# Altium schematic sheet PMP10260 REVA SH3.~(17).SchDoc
size 431 x 279 mm; Date: Not shown in title block; ApprovedBy: Not shown in title block; CheckedBy: Not shown in title block; Author: Not shown in title block; CompanyName: Not shown in title block; Engineer: Not shown in title block; Organization: Not shown in title block; Address1: Not shown in title block; Address2: Not shown in title block; Address3: Not shown in title block; Address4: Not shown in title block; DocumentNumber: 3; Revision: Use project parameter SCH_Rev; SheetNumber: 3; SheetTotal: 4; PageSetup: Record=PageOptions|CenterHorizontal=True|CenterVertical=True|PrintScale=1.00|XCorrection=1.00|YCorrection=1.00|PrintKind=0|BorderSize=5000000|LeftOffset=0|BottomOffset=0|Orientation=2|PaperLength=1000|PaperWidth=1000|Scale=100|PaperSource=15|PrintQuality=600|MediaType=1|DitherType=10|PaperKind=Letter|PrintScaleMode=1
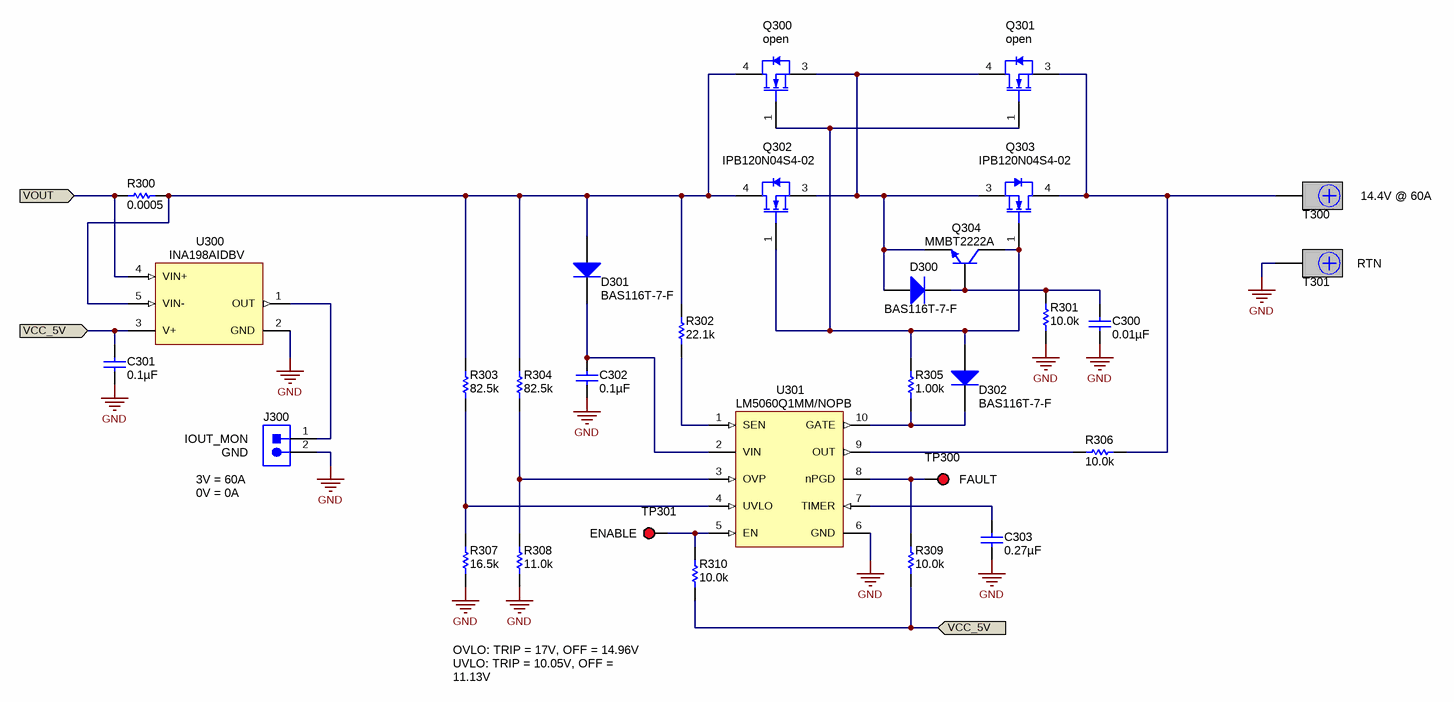
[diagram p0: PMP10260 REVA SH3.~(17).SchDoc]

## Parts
C300  ValueDisplayed: 0.01µF  [0603]  (hidden comment: C1608X7R1H103K)
C301  ValueDisplayed: 0.1µF  [0603L]  (hidden comment: C1608X7R1H104K)
C302  ValueDisplayed: 0.1µF  [0603L]  (hidden comment: C1608X7R1H104K)
C303  ValueDisplayed: 0.27µF  [0805_HV]  (hidden comment: 0805YC274KAT2A)
D300  BAS116T-7-F  [SOT-523]
D301  BAS116T-7-F  [SOT-523]
D302  BAS116T-7-F  [SOT-523]
J300  PEC02SAAN  [CONN_PEC02SAAN]  (value not drawn)
Q300  open  [DDPAK]
Q301  open  [DDPAK]
Q302  IPB120N04S4-02  [DDPAK]
Q303  IPB120N04S4-02  [DDPAK]
Q304  MMBT2222A  [SOT-23]
R300  value 0.0005  [CSS2725_0005]  (hidden comment: CSS2725FTL500)
R301  value 10.0k  [0603]  (hidden comment: CRCW060310K0FKEA)
R302  value 22.1k  [0603]  (hidden comment: CRCW060322K1FKEA)
R303  value 82.5k  [0603]  (hidden comment: CRCW060382K5FKEA)
R304  value 82.5k  [0603]  (hidden comment: CRCW060382K5FKEA)
R305  value 1.00k  [0603]  (hidden comment: CRCW06031K00FKEA)
R306  value 10.0k  [0603]  (hidden comment: CRCW060310K0FKEA)
R307  value 16.5k  [0603]  (hidden comment: CRCW060316K5FKEA)
R308  value 11.0k  [0603]  (hidden comment: CRCW060311K0FKEA)
R309  value 10.0k  [0603]  (hidden comment: CRCW060310K0FKEA)
R310  value 10.0k  [0603]  (hidden comment: CRCW060310K0FKEA)
T300  CB70-14-CY  [CB70-14-CY]  (value not drawn)
T301  CB70-14-CY  [CB70-14-CY]  (value not drawn)
TP300  5010  [Keystone5010]  (value not drawn)
TP301  5010  [Keystone5010]  (value not drawn)
U300  INA198AIDBV  [DBV0005A_N]
U301  LM5060Q1MM/NOPB  [MUB10A_N]

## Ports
VCC_5V, VOUT

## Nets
GND: C300.2 C301.2 C302.2 C303.2 J300.2 R301.1 R307.1 R308.1 T301.1 U300.2(GND) U301.6(GND)
VCC_5V: C301.1 R309.1 R310.1 U300.3(V+) ; port VCC_5V
VOUT: R300.1 U300.4(VIN+) ; port VOUT
NetC300_1: C300.1 D300.3(K) Q304.1(B) R301.2
NetC302_1: C302.1 D301.3(K) U301.2(VIN)
NetC303_1: C303.1 U301.7(TIMER)
NetD300_1: D300.1(A) Q300.3(S) Q301.4(D) Q302.3(S) Q303.3(S) Q304.2(E)
NetD301_1: D301.1(A) Q300.4(D) Q302.4(D) R300.2 R302.2 R303.2 R304.2 U300.5(VIN-)
NetD302_1: D302.1(A) Q300.1(G) Q301.1(G) Q302.1(G) Q303.1(G) Q304.3(C) R305.1
NetD302_3: D302.3(K) R305.2 U301.10(GATE)
NetJ300_1: J300.1 U300.1(OUT)
NetQ301_3: Q301.3(S) Q303.4(D) R306.1 T300.1
NetR302_1: R302.1 U301.1(SEN)
NetR303_1: R303.1 R307.2 U301.4(UVLO)
NetR304_1: R304.1 R308.2 U301.3(OVP)
NetR306_2: R306.2 U301.9(OUT)
NetR309_2: R309.2 TP300.1 U301.8(nPGD)
NetR310_2: R310.2 TP301.1 U301.5(EN)

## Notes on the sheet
- 14.4V @ 60A
- RTN
- (near J300) 3V = 60A
- (near J300) IOUT_MON
- (near J300) GND
- (near TP300) FAULT
- 0V = 0A
- (near TP301) ENABLE
- OVLO: TRIP = 17V, OFF = 14.96V
  UVLO: TRIP = 10.05V, OFF = 11.13V
  OC = 65A/Hot

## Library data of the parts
C300 = C1608X7R1H103K: CAP, CERM, 0.01uF, 50V, +/-10%, X7R, 0603; Manufacturer: TDK; Polarized: N; CompType: Capacitor; U/M: EA; Cap_F: 0.00000001; Tolerance_%: 10; ESR_Ohm: 0.0539; Value1: 0.0539 ohm; VDC_V: 50; TaMin_C: -55; TaMax_C: 125
C301 C302 = C1608X7R1H104K: CAP, CERM, 0.1uF, 50V, +/-10%, X7R, 0603; Manufacturer: TDK; Polarized: N; CompType: Capacitor; U/M: EA; Cap_F: 0.0000001; Tolerance_%: 10; ESR_Ohm: 0.017; Value1: 0.017 ohm; VDC_V: 50; TaMin_C: -55; TaMax_C: 125; Cap_Case: 0603
C303 = 0805YC274KAT2A: CAP, CERM, 0.27uF, 16V, +/-10%, X7R, 0805; Manufacturer: AVX; Polarized: N; CompType: Capacitor; U/M: EA; Cap_F: 0.00000027; Tolerance_%: 10; ESR_Ohm: 0.015; Value1: 0.015 ohm; VDC_V: 16; TaMin_C: -55; TaMax_C: 125; Cap_Case: 0805
D300-D302 = BAS116T-7-F: Diode, Switching, 85V, 0.215A, SOT-523; Manufacturer: Diodes Inc.; U/M: EA; Vf_V: 1.25; Value2: 1.25V; Io_A: 0.215; Vr_V: 85; TJmax_C: 150
J300 = PEC02SAAN: Header, 100mil, 2x1, Tin, TH; Manufacturer: Sullins Connector Solutions; SymbolCreator: a0412235; U/M: EA
Q300 Q301 = IPB100N10S3-05: MOSFET, open, DDPAK; Alternate Manufacturer: None; U/M: EA; ChType: N; Value1: ? ohm; IdsMax_A: 100
Q302 Q303 = IPB100N10S3-05: MOSFET, N-CH, 40V, 120A, DDPAK; Manufacturer: Infineon Technologies; Alternate Manufacturer: None; U/M: EA; ChType: N; VdsMax_V: 40; Value1: ? ohm; Vgs_V: 20; IdsMax_A: 100
Q304 = MMBT2222A, Fairchild Semiconductor: Transistor, NPN, 40V, 0.15A, SOT-23; CompType: BJT; PNP: 0; NPN: 1; Vceo_V: 40; Vcesat1_V: 0.3; Value: 0.3V; IcRated_A: 0.15; HfeMax: 300; TaMin_C: -55; TaMax_C: 150; U/M: EA
R300 = CSS2725FTL500: RES, 0.0005 ohm, 1%, 4W, RES_2725; Manufacturer: Stackpole Electronics Inc; CompType: Resistor; Value_Code: R0005; Tolerance_%: 1; Power_W: 4; TempCo: 50 ppm/C; U/M: EA
R301 R306 R309 R310 = CRCW060310K0FKEA: RES, 10.0k ohm, 1%, 0.1W, 0603; Manufacturer: Vishay-Dale; CompType: Resistor; Res_ohm: 10000; Value_Code: 10k0; Tolerance_%: 1; Power_W: 0.1; VDC_V: 75; TempCo: 100 ppm/C; EIA_Code: E96; U/M: EA
R302 = CRCW060322K1FKEA: RES, 22.1k ohm, 1%, 0.1W, 0603; Manufacturer: Vishay-Dale; CompType: Resistor; Res_ohm: 22100; Value_Code: 22k1; Tolerance_%: 1; Power_W: 0.1; VDC_V: 75; TempCo: 100 ppm/C; EIA_Code: E96; U/M: EA
R303 R304 = CRCW060382K5FKEA: RES, 82.5k ohm, 1%, 0.1W, 0603; Manufacturer: Vishay-Dale; CompType: Resistor; Res_ohm: 82500; Value_Code: 82k5; Tolerance_%: 1; Power_W: 0.1; VDC_V: 75; TempCo: 100 ppm/C; EIA_Code: E96; U/M: EA
R305 = CRCW06031K00FKEA: RES, 1.00k ohm, 1%, 0.1W, 0603; Manufacturer: Vishay-Dale; CompType: Resistor; Res_ohm: 1000; Value_Code: 1k00; Tolerance_%: 1; Power_W: 0.1; VDC_V: 75; TempCo: 100 ppm/C; EIA_Code: E96; U/M: EA
R307 = CRCW060316K5FKEA: RES, 16.5k ohm, 1%, 0.1W, 0603; Manufacturer: Vishay-Dale; CompType: Resistor; Res_ohm: 16500; Value_Code: 16k5; Tolerance_%: 1; Power_W: 0.1; VDC_V: 75; TempCo: 100 ppm/C; EIA_Code: E96; U/M: EA
R308 = CRCW060311K0FKEA: RES, 11.0k ohm, 1%, 0.1W, 0603; Manufacturer: Vishay-Dale; CompType: Resistor; Res_ohm: 11000; Value_Code: 11k0; Tolerance_%: 1; Power_W: 0.1; VDC_V: 75; TempCo: 100 ppm/C; EIA_Code: E96; U/M: EA
T300 T301 = CB70-14-CY: Terminal 90A Lug; Manufacturer: Panduit; SymbolCreator: crossc; CompType: Screw Terminal; U/M: EA
TP300 TP301 = 5010: Test Point, Multipurpose, Red, TH; Manufacturer: Keystone; CompType: Test Point Loop; U/M: EA
U300 = INA198AIDBV: CURRENT SHUNT MONITOR -16V to +80V Common-Mode Range, DBV0005A; Alternate Manufacturer: None; Manufacturer: Texas Instruments; SymbolCreator: a0411947; CompType: IC; U/M: EA
U301 = LM5060Q1MM/NOPB: High-Side Protection Controller with Low Quiescent Current, 10-pin MSOP, Pb-Free; Manufacturer: National Semiconductor; PackageTopMarking: ZXTT*SZAB; PowerWise: N; CompType: Switcher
